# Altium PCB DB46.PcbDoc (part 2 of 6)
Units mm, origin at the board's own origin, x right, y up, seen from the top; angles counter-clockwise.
Board outline 82.2 x 113.2 mm, 8 copper layers (Top Layer, MidLayer1, MidLayer2, GND, MidLayer3, VCC, MidLayer4, Bottom Layer), stack 1.576 mm thick; 186 components, 477 nets, 1727 pads, 1538 vias.
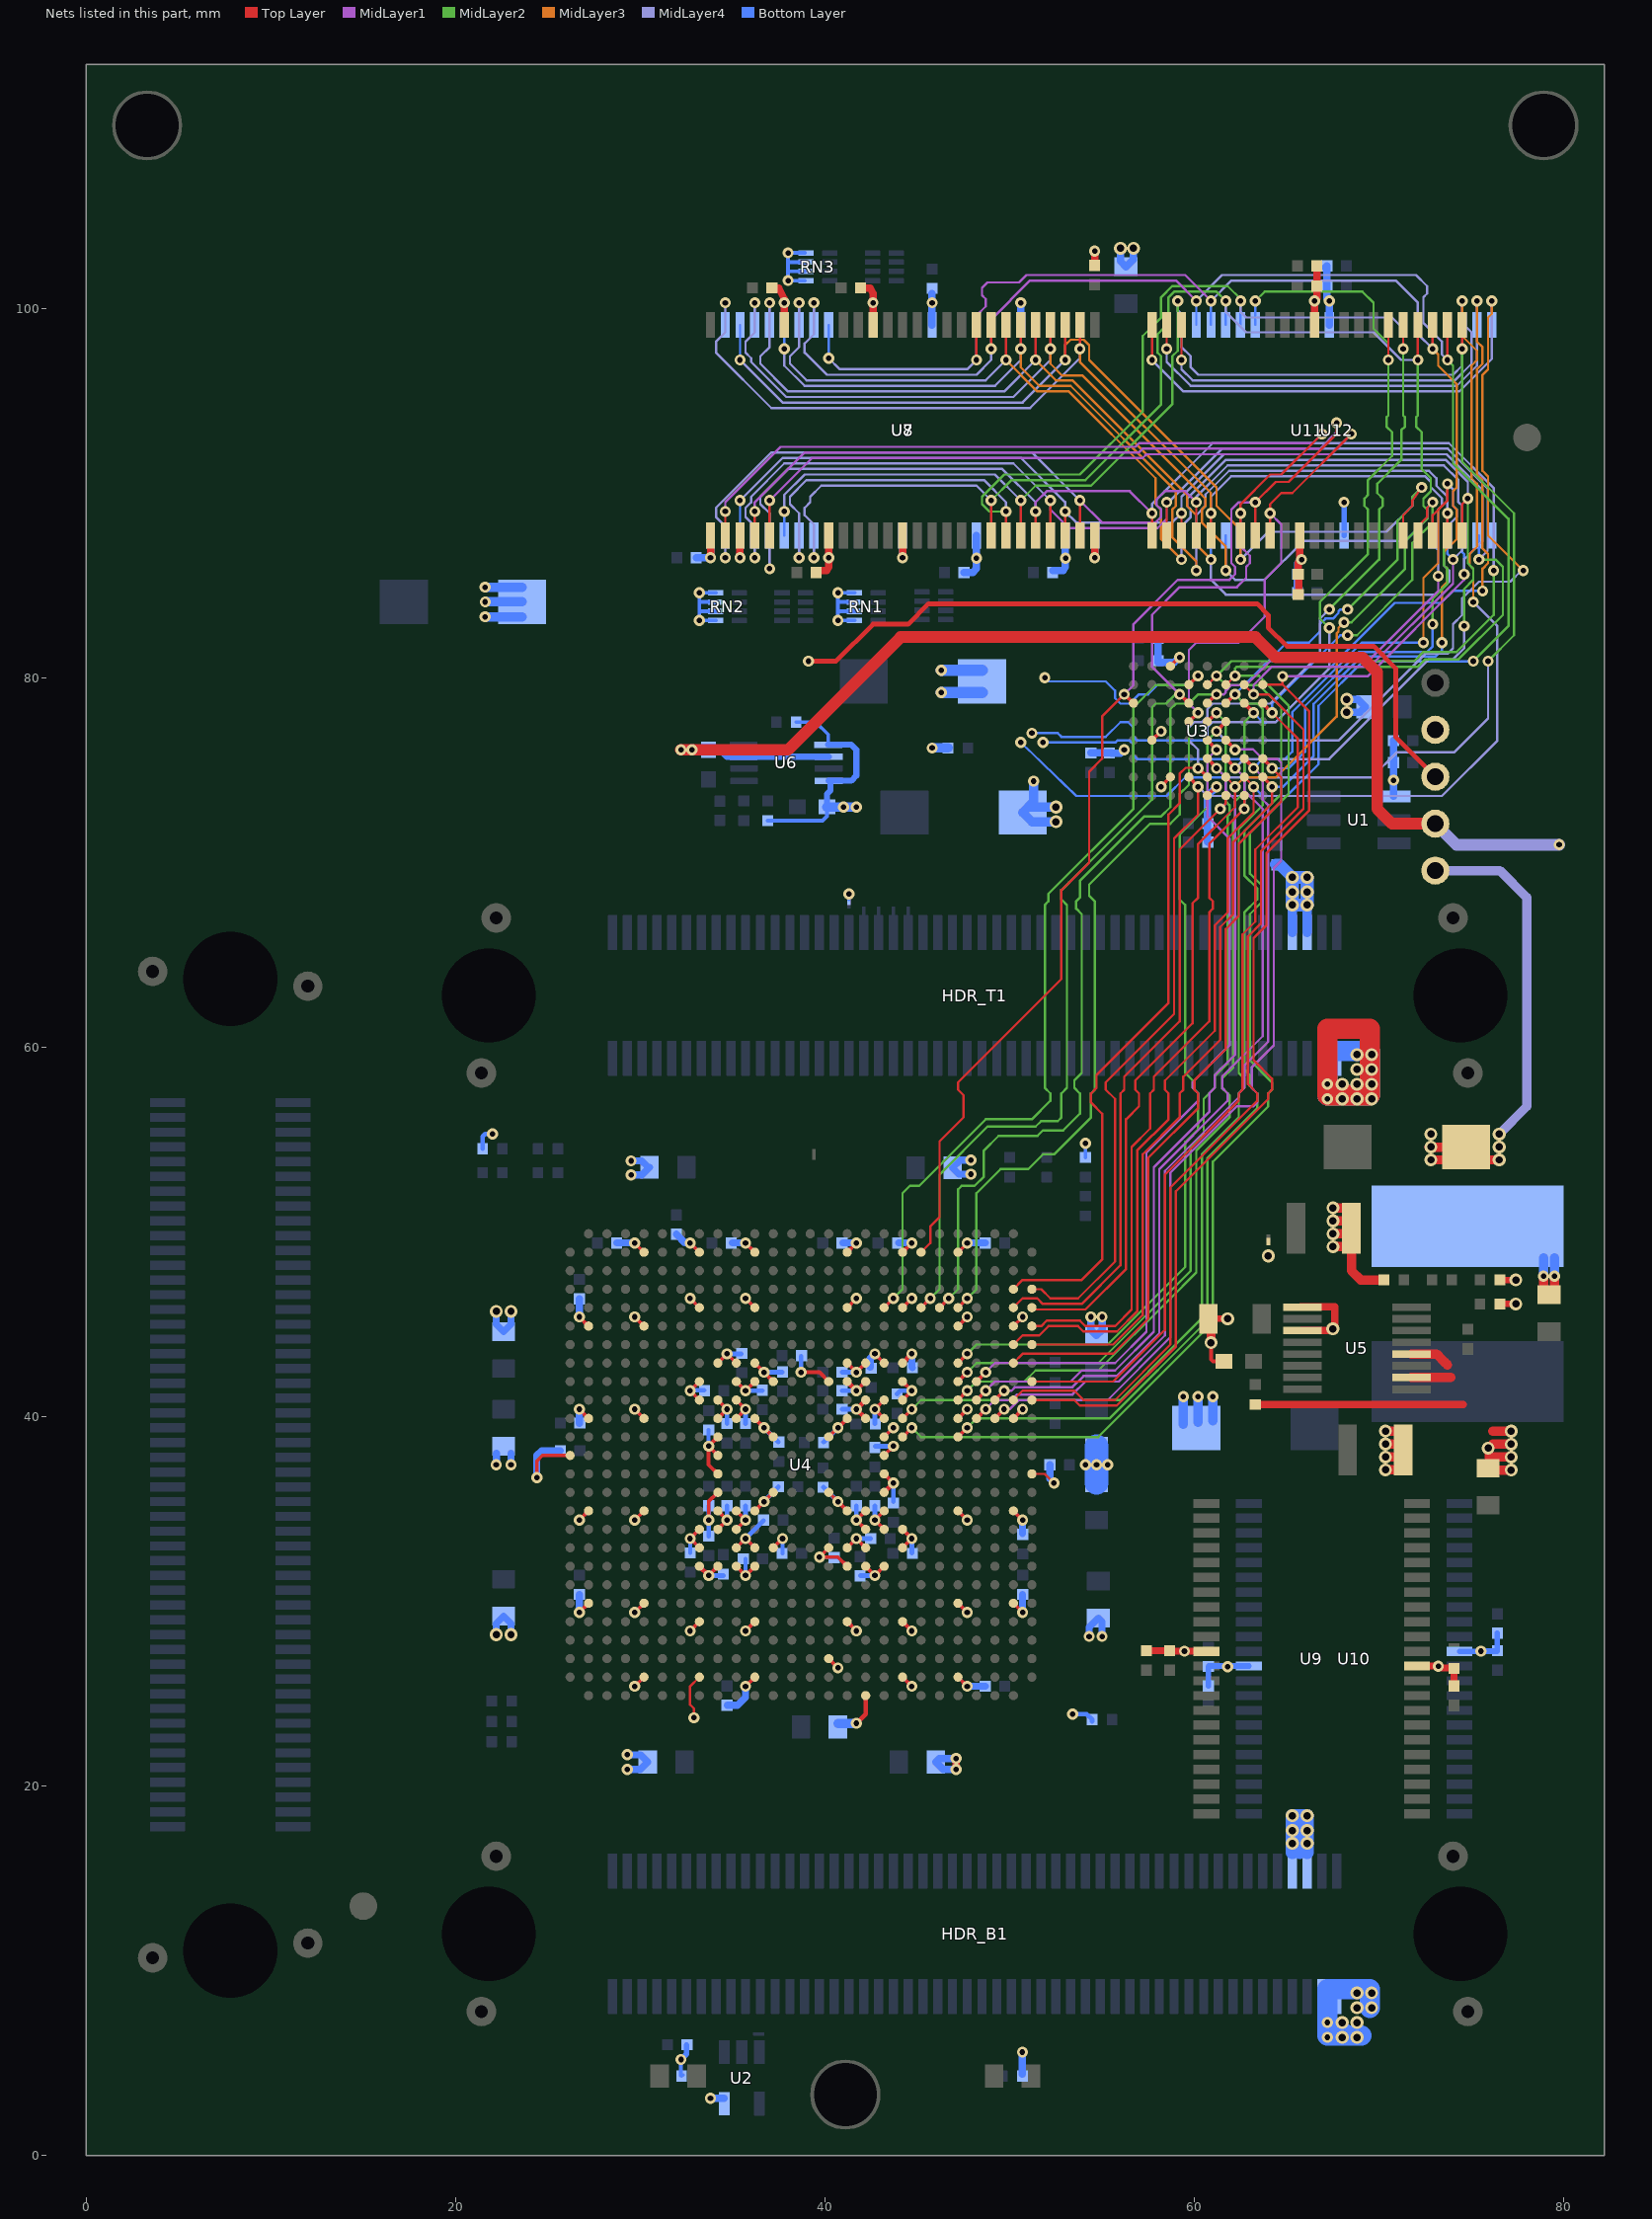
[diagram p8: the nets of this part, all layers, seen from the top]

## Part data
"Altium Logo Bot1" "Altium Logo Top1": library part D-000-0003, "Altium Logo for PCB"
C1 C7 C8 C9 C10 C11 C12 C13 C14 C25 C26 C27 C40 C41 C42 C43 C44 C71 C72 C73 C77 C91 C92 C93 C94 C99 C100 C103 C104 C107 C108 C109 C110: library part D-101-0080, "Capacitor, Ceramic, 0.1uF 10% 16V 0402 (1005) X7R"
C2 C15 C16 C17 C18 C19 C20 C21 C22 C28 C29 C30 C31 C45 C46 C47 C48 C49 C50 C51 C52 C53 C54 C55 C56 C57 C58 C59 C60 C61 C62 C63 C64 C65 C66 C67 C68 C74 C75 C76 C95 C96 C97 C98 C101 C102 C105 C106 C111 C112 C113 C114: library part D-101-0077, "Capacitor, Ceramic, 10nF 10% 16V 0402 (1005) X7R"
C3 C23 C69 C70 C82: library part D-101-0088, "Capacitor, Tantalum, 220uF 10% 10V MCCT-D (7343-31)"
C4 C5 C6 C24 C32 C33 C34 C35 C36 C37 C38 C39 C78 C79 C83 C85: library part D-101-0087, "Capacitor, Ceramic, 10uF 10% 10V 0805 (2012) X5R"
C80: library part D-101-0069, "Capacitor, Ceramic, 470pF 5% 50V 0402 (1005) COG"
C81 C88 C89: library part D-101-0095, "Capacitor, Ceramic, 2.2uF 10% 10V 0603 (1608) X5R"
C84 C86: library part D-101-0021, "Capacitor, Ceramic, 22uF -20%/+80% 10V 1210 (3225) Y5V"
C87: library part D-101-0027, "Capacitor, Ceramic, 1uF 10% 25V 1206 (3216) X7R"
C90: library part D-101-0105, "Capacitor, Ceramic, 0.033uF 10% 10V 0402 (1005) X7R"
FD1 FD2: library part D-000-0005, "Fiducial - Round 1.5mm Top-Bottom"
HDR_B1 HDR_L1 HDR_T1: library part D-300-0025, "Connector, Molex Docking Station 100 Pin Male 54075"
L1: library part D-102-0004, "Inductor, 2.2uH, 15A, 4R2, SMD"
LED1: library part D-153-0004, "LED, Green 0805 (2012) KP-2012SGD"
LED2: library part D-153-0003, "LED, Red 0805 (2013) HSMH-C170"
MH1 MH2 MH3: library part D-001-0001, "Mounting Hole, M3 Screw, Plated, Square Pad"
NT1 NT2 NT3 NT4 NT5 NT6 NT7 NT8: library part D-002-0002, "Net-Tie, Surface Mount, 2 x 0.4mm x 0.2mm SMT Pads - For 0.2mm Track"
PCB1: library part D-810-0034, "DB46 Blank PCB - Daughter Board"
R1 R2: library part D-100-0111, "Resistor, 270R 1% 0402 (1005)"
R3 R5 R8 R11: library part D-100-0088, "Resistor, 4K7 1% 0402 (1005)"
R4 R6 R7 R9 R10 R12 R13 R14 R15 R16 R17: library part D-100-0131, "Resistor, 100R 1% 0402 (1005)"
R22 R27 R28 R29: library part D-100-0132, "Resistor, 100K 1% 0402 (1005)"
R23: library part D-100-0128, "Resistor, 10R 1% 0402 (1005)"
R24 R26: library part D-100-0105, "Resistor, 2K7 1% 0402 (1005)"
R25: library part D-100-0109, "Resistor, 27K 1% 0402 (1005)"
RN1 RN2 RN3 RN4 RN5 RN6: library part D-104-0001, "Resistor Network, Isolated, 4 x 100R, 5%, SMD 0402 x 4"
TP1 TP2 TP3 TP4 TP5: library part D-006-0000, "Test Point, PCB Mount with Silkscreen Box"
U1: library part D-263-0002, "Dual Addressable Switch Plus 1KB Memory"
U2: library part D-205-0001, "SN74LVC1G04DBV, Single Inverter Gate, 1.65-V to 5.5-V"
U3: library part D-262-0001, "S29GL256N11FFIV10, 256 Megabit (16M x 16) 3.0V Page Mode Flash Memory"
U4: library part D-241-0021, "FPGA, Xilinx Virtex-4, XC4VSX35"
U5: library part D-204-0002, "MAX1831EEE, 3A, 1MHz, Low-Voltage, Step-Down Regulators with Synchronous Rectification and Internal Switches"
U6: library part D-204-0016, "MAX8860EUA18+, 1.8V Linear Regulator with adjustable Output, Low-noise, Low-dropout, 300mA, uMAX"
U7 U8: library part D-261-0000, "MT48LC16M16A2TG, 256 Mbit High-Speed CMOS SDRAM, 16Mb x 16Bit x 4 Banks, TSOP54"
U9 U10 U11 U12: library part D-260-0000, "K6R4016V1D-TC10T, 256K x 16-Bit SRAM, TSOP44"

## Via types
v1: diameter 0.6, hole 0.3, Top Layer to Bottom Layer, 904 vias
v2: diameter 0.6, hole 0.3, Top Layer to Bottom Layer, tented both sides, 506 vias
v3: diameter 0.7, hole 0.4, Top Layer to Bottom Layer, 127 vias
v4: diameter 0.6, hole 0.3, Top Layer to Bottom Layer, tented top, 1 vias

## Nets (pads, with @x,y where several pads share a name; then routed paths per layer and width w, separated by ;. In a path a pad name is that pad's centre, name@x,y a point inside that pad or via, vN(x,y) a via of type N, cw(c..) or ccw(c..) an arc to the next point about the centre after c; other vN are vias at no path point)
1V2: C3.1 C4.1 C5.1 C6.1 C7.1 C8.1 C9.1 C10.1 C11.1 C12.1 C13.1 C14.1 C15.1 C16.1 C17.1 C18.1 C19.1 C20.1 C21.1 C22.1 C82.1 C85.1 C86.1 L1.2 R24.1 TP5.1 U4.J10 U4.J11 U4.J16 U4.J17 U4.K9 U4.K10 U4.K17 U4.K18 U4.L9 U4.L10 U4.L11 U4.L16 U4.L17 U4.L18 U4.M12 U4.M15 U4.R12 U4.R15 U4.T9 U4.T10 U4.T11 U4.T16 U4.T17 U4.T18 U4.U9 U4.U10 U4.U17 U4.U18 U4.V10 U4.V11 U4.V16 U4.V17 | length 82.6
  Top Layer w0.2: U4.U9@34.2,33.9 v1(34.7,34.4) U4.T9@34.2,34.9 ; U4.L9@34.2,39.9 v1(34.7,40.4) U4.K9@34.2,40.9 ; U4.V10@35.2,32.9 v1(35.7,33.4) U4.V11@36.2,32.9 ; U4.U10@35.2,33.9 v1(35.7,34.4) U4.T10@35.2,34.9 ; U4.L10@35.2,39.9 v1(35.7,40.4) U4.K10@35.2,40.9 ; U4.J10@35.2,41.9 v1(35.7,41.4) U4.J11@36.2,41.9 ; U4.T11@36.2,34.9 v1(36.7,35.4) U4.R12@37.2,35.9 ; U4.L11@36.2,39.9 U4.M12@37.2,38.9 ; U4.R15@40.2,35.9 v1(40.7,35.4) U4.T16@41.2,34.9 ; U4.M15@40.2,38.9 U4.L16@41.2,39.9 ; U4.V16@41.2,32.9 v1(41.7,33.4) U4.V17@42.2,32.9 ; v1(41.7,41.4) U4.J17@42.2,41.9 ; U4.U17@42.2,33.9 v1(41.7,34.4) U4.T17@42.2,34.9 ; U4.U18@43.2,33.9 v1(42.7,34.4) U4.T18@43.2,34.9 ; U4.L18@43.2,39.9 v1(42.7,40.4) U4.K18@43.2,40.9
  Top Layer w0.254: U4.J16@41.2,41.9 v1(41.7,41.4) ; U4.L17@42.2,39.9 v1(41.7,40.4) U4.K17@42.2,40.9
  Top Layer w0.5: C86.1@68.4,50.2 C86.1@68.45,50.15 ; C86.1@68.5,49.5 68.5,50.2 68.5,47.9 69,47.4 R24.1@70.262,47.4 ; v3(72.8,53.9) C82.1@74,53.9 ; C82.1@74.709,53.9 v3(76.5,53.9) ; C82.1@74.709,54.6 C82.1@74.702,54.593 C82.1@75.395,53.9 ; C85.1@78.9,46.6 v1(78.9,47.6) ; C85.1@79.5,46.6 v1(79.5,47.6)
  Top Layer w0.508: v3(67.5,49.2) C86.1@68.5,49.2 ; v3(67.5,49.9) C86.1@68.5,49.9 ; v3(67.5,50.6) C86.1@68.5,50.6 ; v3(67.5,51.3) C86.1@68.5,51.3 ; v3@72.707,54.593 C82.1@74.702,54.593
  MidLayer4 w0.508: TP5.1@73.043,69.562 76.538,69.562 78,68.1 78,56.8 v3(76.5,55.3)
  Bottom Layer w0.2: v1(36.7,35.4) v1@36.7,35.425 ; v1@40.6,35.4 v1(40.7,35.4)
  Bottom Layer w0.254: v1(34.7,34.4) C19.1@34.7,35.175 ; C22.1@34.7,39.625 v1(34.7,40.4) ; v1(35.7,33.4) C11.1@36.675,34.375 ; v1(35.7,34.4) C20.1@35.7,35.175 ; C14.1@35.7,39.625 v1(35.7,40.4) ; v1(35.7,41.4) C18.1@36.6,41.4 ; v1@36.7,35.425 C9.1@37.475,36.2 ; v1(36.7,39.4) C13.1@37.475,38.625 ; C15.1@39.925,36.175 v1(40.7,35.4) ; C10.1@39.925,38.625 v1(40.7,39.4) ; C21.1@40.925,40.4 v1(41.7,40.4) ; C12.1@40.925,41.4 v1(41.7,41.4) ; v1(41.7,33.4) C7.1@42.475,33.4 ; v1(41.7,34.4) C8.1@41.7,35.175 ; v1(42.7,34.4) C16.1@42.7,35.175 ; C17.1@42.7,39.625 v1(42.7,40.4)
  Bottom Layer w0.4: v1(22.2,37.4) C4.1@22.2,38 ; v1(23,37.4) C4.1@23,38
  Bottom Layer w0.5: v1(78.9,47.6) L1.2@78.9,48.6 ; v1(79.5,47.6) L1.2@79.5,48.6
  Bottom Layer w0.508: C3.1@59.4,39.586 v1(59.4,41.086) ; C3.1@60.2,39.686 v1(60.2,41.086) ; C3.1@61,39.786 v1(61,41.086)
  Bottom Layer w1.27: C6.1@54.7,38.4 54.701,38.399 C5.1@54.701,36.4
  other v1: 54.1,37.4 54.701,37.4 55.3,37.4
  other v3: 72.8,54.6 76.5,54.6 72.8,55.3
2V5: C23.1 C24.1 C25.1 C26.1 C27.1 C28.1 C29.1 C30.1 C31.1 C88.1 R22.2 R28.1 TP3.1 U4.AF17 U4.H11 U4.H16 U4.H17 U4.J12 U4.M9 U4.N9 U4.N18 U4.P9 U4.P18 U4.R18 U4.V15 U4.W10 U4.W11 U4.W16 U6.1 U6.4 | length 81.1
  Top Layer w0.2: 33.7,37.4 U4.P9@34.2,36.9 ; v1(33.7,38.4) U4.N9@34.2,37.9 ; U4.H11@36.2,42.9 v1(36.7,42.4) U4.J12@37.2,41.9 ; U4.H16@41.2,42.9 v1(41.7,42.4) U4.H17@42.2,42.9 ; U4.N18@43.2,37.9 v1(43.7,38.4)
  Top Layer w0.203: 33.7,37.4 v1(33.7,38.4) U4.M9@34.2,38.9 ; U4.W10@35.2,31.9 v1(35.7,31.4) U4.W11@36.2,31.9 ; U4.V15@40.2,32.9 v1(39.7,32.4) 40.7,32.4 U4.W16@41.2,31.9 ; U4.P18@43.2,36.9 v1(43.7,36.4)
  Top Layer w0.254: v2(39.1,80.9) 40.6,80.9 42.6,82.9 44.5,82.9 45.6,84 63.4,84 64,83.4 64,82.7 65,81.7 69.7,81.7 70.9,80.5 70.9,77.331 70.9,76.785 TP3.1@73.043,74.642 ; v1(41.7,23.4) 42.2,23.9 U4.AF17@42.2,24.9 ; U4.R18@43.2,35.9 v1(43.7,36.4)
  Bottom Layer w0.2: v1(43.7,38.4) v1@43.7,38.6
  Bottom Layer w0.203: v1(33.7,38.4) C29.1@33.7,39.275 ; v1(35.7,31.4) C31.1@35.7,32.3 ; R22.2@36.9,72.262 39.862,72.262 40.1,72.5 C88.1@40.1,73 ; R28.1@38.438,77.6 39.5,77.6 40.175,76.925 U6.1@40.175,76.375 ; v1(39.7,32.4) C27.1@40.475,32.4
  Bottom Layer w0.254: v1(36.7,42.4) C28.1@37.675,42.4 ; C25.1@40.925,42.4 v1(41.7,42.4) ; C26.1@42.725,38.4 v1(43.7,38.4) ; C30.1@43.7,35.4 v1@43.7,36.175
  Bottom Layer w0.33: C88.1@40.1,73 40.1,73.7 40.3,73.9 U6.4@40.3,74.425 ; U6.1@40.175,76.375 41.425,76.375 41.7,76.1 41.7,74.7 41.425,74.425 U6.4@40.2,74.425
  Bottom Layer w0.508: C88.1@40.1,73 v2(41.7,73) ; C24.1@40.7,23.4 v1(41.7,23.4)
  Bottom Layer w0.635: v2(46.3,79.2) C23.1@48.5,79.2 ; v2(46.3,80.4) C23.1@48.5,80.4
  other v2: 41,73
3V3: C1.2 C2.1 C32.1 C33.1 C34.1 C35.1 C36.1 C37.1 C38.1 C39.1 C40.1 C41.1 C42.1 C43.1 C44.1 C45.1 C46.1 C47.1 C48.1 C49.1 C50.1 C51.1 C52.1 C53.1 C54.1 C55.1 C56.1 C57.1 C58.1 C59.1 C60.1 C61.1 C62.1 C63.1 C64.1 C65.1 C66.1 C67.1 C68.1 C69.1 C70.1 C71.2 C72.1 C73.1 C74.1 C75.1 C76.1 C77.1 C78.1 C79.1 C91.1 C92.1 C93.1 C94.1 C95.1 C96.1 C97.1 C98.1 C99.1 C100.1 C101.1 C102.1 C103.1 C104.1 C105.1 C106.1 C107.1 C108.1 C109.1 C110.1 C111.1 C112.1 C113.1 C114.1 HDR_B1.94 HDR_B1.96 HDR_T1.94 HDR_T1.96 NT1.2 R1.1 R2.1 R3.2 R5.2 R8.2 R11.2 RN1.1 RN1.2 RN1.3 RN1.4 RN2.1 RN2.2 RN2.3 RN2.4 RN3.1 RN3.2 RN3.3 RN3.4 TP2.1 U1.4 U2.5 U3.D8 U3.F1 U3.F7 U3.G5 U4.AA2 U4.AA5 U4.AA22 U4.AA25 U4.AB8 U4.AB11 U4.AB16 U4.AB19 U4.AD15 U4.AE5 U4.AE8 U4.AE11 U4.AE19 U4.AE22 U4.B5 U4.B8 U4.B11 U4.B16 U4.B19 U4.B22 U4.E8 U4.E11 U4.E16 U4.E19 U4.F2 U4.F5 U4.F22 U4.F25 U4.H9 U4.H10 U4.H18 U4.H19 U4.J8 U4.J15 U4.J19 U4.K8 U4.K19 U4.L2 U4.L5 U4.L22 U4.L25 U4.M18 U4.N1 U4.P26 U4.R9 U4.T2 U4.T5 U4.T22 U4.T25 U4.U8 U4.U19 U4.V8 U4.V12 U4.V19 U4.W8 U4.W9 U4.W17 U4.W18 U7.1 U7.3 U7.9 U7.14 U7.27 U7.43 U7.49 U8.1 U8.3 U8.9 U8.14 U8.27 U8.43 U8.49 U9.11 U9.33 U10.11 U10.33 U11.11 U11.33 U12.11 U12.33 | length 216.2
  Top Layer w0.127: v1(32.9,23.7) 32.9,24.2 32.7,24.4 32.7,25.4 U4.AE8@33.2,25.9 ; U7.9@40.2,87.2 U7.9@40.2,87.7 ; U4.P26@51.2,36.9 51.9,36.9 v1(52.4,36.4)
  Top Layer w0.178: v1(29.7,49.4) U4.B5@30.2,48.9 ; U4.B22@47.2,48.9 v1(47.7,49.4) ; U4.AA25@50.2,29.9 v1(50.7,29.4) ; U4.F25@50.2,44.9 v1(50.7,45.4)
  Top Layer w0.2: v1(24.4,36.7) 24.4,37.6 24.7,37.9 U4.N1@26.2,37.9 ; v1(26.7,29.4) U4.AA2@27.2,29.9 ; v1(26.7,34.4) U4.T2@27.2,34.9 ; v1(26.7,40.4) U4.L2@27.2,39.9 ; v1(26.7,45.4) U4.F2@27.2,44.9 ; v1(29.7,25.4) U4.AE5@30.2,25.9 ; v1(29.7,29.4) U4.AA5@30.2,29.9 ; v1(29.7,34.4) U4.T5@30.2,34.9 ; v1(29.7,40.4) U4.L5@30.2,39.9 ; v1(29.7,45.4) U4.F5@30.2,44.9 ; v1(32.7,28.4) U4.AB8@33.2,28.9 ; v1(32.7,46.4) U4.E8@33.2,45.9 ; v1(32.7,49.4) U4.B8@33.2,48.9 ; U4.V8@33.2,32.9 v1(32.7,33.4) U4.U8@33.2,33.9 ; U4.K8@33.2,40.9 v1(32.7,41.4) U4.J8@33.2,41.9 ; v1(33.7,34.4) 33.7,35.4 U4.R9@34.2,35.9 ; U4.H9@34.2,42.9 v1(34.7,43.4) U4.H10@35.2,42.9 ; v1(35.7,25.4) U4.AE11@36.2,25.9 ; v1(35.7,28.4) U4.AB11@36.2,28.9 ; v1(35.7,46.4) U4.E11@36.2,45.9 ; v1(35.7,49.4) U4.B11@36.2,48.9 ; U4.V12@37.2,32.9 v1(37.7,33.4) ; v1(38.7,42.4) 39.7,42.4 U4.J15@40.2,41.9 ; U4.AD15@40.2,26.9 v1(40.7,26.4) ; U4.AB16@41.2,28.9 v1(41.7,28.4) ; U4.E16@41.2,45.9 v1(41.7,46.4) ; U4.B16@41.2,48.9 v1(41.7,49.4) ; U4.W17@42.2,31.9 v1(42.7,31.4) U4.W18@43.2,31.9 ; v1(42.7,43.4) U4.H18@43.2,42.9 ; U4.M18@43.2,38.9 v1(43.7,39.4) ; U4.AE19@44.2,25.9 v1(44.7,25.4) ; U4.AB19@44.2,28.9 v1(44.7,28.4) ; U4.V19@44.2,32.9 v1(44.7,33.4) U4.U19@44.2,33.9 ; U4.K19@44.2,40.9 v1(44.7,41.4) U4.J19@44.2,41.9 ; U4.E19@44.2,45.9 v1(44.7,46.4) ; U4.B19@44.2,48.9 v1(44.7,49.4) ; U4.AE22@47.2,25.9 v1(47.7,25.4) ; U4.AA22@47.2,29.9 v1(47.7,29.4) ; U4.T22@47.2,34.9 v1(47.7,34.4) ; U4.L22@47.2,39.9 v1(47.7,40.4) ; U4.F22@47.2,44.9 v1(47.7,45.4) ; U4.T25@50.2,34.9 v1(50.7,34.4) ; U4.L25@50.2,39.9 v1(50.7,40.4) ; U3.G5@57.7,76.625 v1(58.2,77.1) ; v1@58.2,74.125 U3.F7@58.7,74.625 ; U3.F1@58.7,80.625 v1@59.2,81.125 ; U3.D8@60.7,73.625 v1@61.2,74.125
  Top Layer w0.203: v1(33.7,31.4) U4.W9@34.2,31.9
  Top Layer w0.254: U4.W8@33.2,31.9 v1(33.7,31.4) ; U4.H19@44.2,42.9 v1(44.7,43.4)
  Top Layer w0.381: v1(47.1,20.9) v1(47.1,21.5) ; C102.1@57.4,27.325 C100.1@58.652,27.325 58.672,27.305 59.512,27.305 59.517,27.3 U9.33@60.652,27.3 ; U9.11@72.052,26.5 73.3,26.5 73.4,26.4 74.027,26.4 C99.1@74.052,26.375 C101.1@74.052,25.425 ; v1@73.195,26.5 v1(73.203,26.492)
  Top Layer w0.4: v2@33.8,86.6 U7.1@33.8,87.7 ; v2(35.4,86.5) U7.3@35.4,87.7 ; C95.1@37.125,101.1 37.5,101.1 37.8,100.5 v2@37.8,100.2 ; U7.49@37.8,99.1 v2(37.8,100.3) ; C92.1@39.525,85.8 40.1,85.8 40.2,86 40.2,86.1 40.22,86.399 40.223,86.445 40.225,86.475 v2@40.219,86.504 ; U7.9@40.2,87.7 v2@40.2,86.6 ; C96.1@41.925,101.1 42.45,101.1 42.6,100.8 v2@42.6,100.2 ; U7.43@42.6,99.1 v2(42.6,100.3) ; v2(44.2,86.5) U7.14@44.2,87.7 ; v2(54.6,86.5) U7.27@54.6,87.7 ; C91.1@54.6,102.325 v2(54.6,103.1) ; C111.1@65.593,85.625 C111.1@65.618,85.6 65.618,86.218 v2(65.8,86.4) 65.7,86.5 U11.11@65.7,87.7 ; C107.1@65.643,84.575 65.643,85.6 C111.1@65.642,85.604 ; U11.33@66.5,99.1 v2(66.5,100.4) 66.625,100.525 C108.1@66.625,102.3 ; v2@40.2,86.6 v2@40.219,86.504 ; v2@40.2,86.6 v2@40.219,86.504
  MidLayer4 w0.127: v3@65.3,16.8 v3(65.3,16.9)
  Bottom Layer w0.2: v1@21.996,55.3 v1@21.996,55.321 ; v1(32.2,5.2) 32.2,4.338 R1.1@32.238,4.3 R1.1@32.3,4.362 ; C71.2@32.5,5.975 C71.2@32.525,6 ; C40.1@32.7,32.625 v1(32.7,33.4) ; 33.2,83.6 RN2.2@34.1,83.6 ; 33.2,84.1 RN2.3@34.1,84.1 ; RN2.1@34.1,83.1 v1(33.2,83.1) v1(33.2,84.6) RN2.4@34.1,84.6 ; U2.5@34.525,3.1 U2.5@34.55,3.125 ; C67.1@37.7,32.6 v1(37.7,33.4) ; 38,102 RN3.2@38.9,102 ; 38,102.5 RN3.3@38.9,102.5 ; RN3.1@38.9,101.5 v1(38,101.5) v1(38,103) RN3.4@38.9,103 ; 40.7,83.6 RN1.2@41.6,83.6 ; 40.7,84.1 RN1.3@41.6,84.1 ; NT1.2@41.3,68 v2(41.3,68.3) ; RN1.1@41.6,83.1 v1(40.7,83.1) v1(40.7,84.6) RN1.4@41.6,84.6 ; v1(47.1,21.5) v1@47.1,21.7 ; R5.2@54.1,54.038 v1(54.1,54.8) v1@54.1,54.9
  Bottom Layer w0.25: R3.2@21.462,54.5 21.462,55.162 21.6,55.3 v1@21.996,55.3 ; R11.2@54.462,23.5 R11.2@54.462,23.538
  Bottom Layer w0.254: v1@32.7,41.425 C53.1@33.45,41.425 ; v1(33.7,31.4) C56.1@34.5,31.4 ; C59.1@33.7,33.525 v1(33.7,34.4) C66.1@33.7,35.175 ; v1(34.7,43.4) C63.1@35.475,43.4 ; v1(38.7,42.4) C61.1@38.7,43.275 ; C58.1@41.925,31.4 v1(42.7,31.4) ; C52.1@43.9,41.225 44.075,41.4 v1(44.7,41.4) ; C65.1@44.7,32.625 v1(44.7,33.4) ; 52.176,36.624 v1(52.4,36.4) ; v1(53.4,23.9) 54.162,23.9 R11.2@54.462,23.6
  Bottom Layer w0.3: v1(32.2,5.2) 32.5,5.5 C71.2@32.5,5.975 ; C103.1@60.752,25.425 C105.1@60.752,26.475 60.777,26.5 U10.11@62.952,26.5 ; v1(61.798,26.467) v1@61.831,26.5 ; U12.11@68.1,87.7 v2(68.1,89.5) ; U10.33@74.352,27.3 75.509,27.3 v1(75.514,27.305) 76.38,27.305 C106.1@76.4,27.325 C104.1@76.4,28.275
  Bottom Layer w0.381: v3(22.2,28.2) 22.2,28.8 C35.1@22.6,29.2 23,28.8 v3(23,28.2) ; v3(22.2,45.7) 22.2,45 C33.1@22.6,44.6 23,45 v3(23,45.7) ; v1(24.4,36.7) 24.4,37.9 24.65,38.15 C55.1@25.674,38.15 ; v1(26.7,29.4) C57.1@26.699,30.375 ; v1(26.7,45.4) C44.1@26.699,46.375 ; C68.1@28.724,49.4 v1(29.7,49.4) ; v2(29.3,20.9) 30,20.9 C39.1@30.4,21.3 30,21.7 v2(29.3,21.7) ; v1(29.503,53.086) 30.086,53.086 C32.1@30.5,53.5 ; v1(29.503,53.848) 30.074,53.848 C32.1@30.404,53.518 ; C54.1@31.95,49.875 32.425,49.4 v1(32.7,49.4) ; C49.1@34.7,24.374 35.274,24.374 35.7,24.8 v1(35.7,25.4) ; C47.1@34.975,49.4 v1(35.7,49.4) ; C51.1@40.976,49.4 v1(41.7,49.4) ; C43.1@43.975,49.4 v1(44.7,49.4) ; v1(44.7,43.4) 44.7,42.675 C41.1@44.725,42.65 ; C38.1@46,21.3 46.4,20.9 v1(47.1,20.9) ; v1(47.7,49.4) C48.1@48.675,49.4 ; v1@47.701,25.399 C45.1@48.675,25.399 ; v1(47.9,53.127) 47.251,53.127 C34.1@46.903,53.474 47.317,53.889 v1(47.9,53.889) ; v1(50.7,29.4) C62.1@50.701,30.375 ; C64.1@50.701,33.675 v1(50.7,34.4) ; 52.176,36.624 C60.1@52.176,37.4 ; v1(54.3,28.1) 54.3,28.6 C37.1@54.8,29.1 55,28.9 v1(55,28.1)
  Bottom Layer w0.4: C42.1@26.7,39.65 v1(26.7,40.4) ; v1(32.7,41.4) v1@32.7,41.425 ; C93.1@33.025,86.5 v2(33.8,86.5) ; U8.27@33.775,87.325 U8.27@33.8,87.3 ; v1(33.8,3.1) U2.5@34.525,3.1 ; v2@33.8,86.475 U8.27@33.8,87.7 ; C50.1@42.45,42.675 42.45,43.15 v1(42.7,43.4) ; v2(44.2,86.5) U8.14@44.2,87.7 ; U8.43@45.8,99.1 C94.1@45.8,100.8 ; C38.1@46,21.3 46.2,21.5 v1(47.1,21.5) ; C98.1@47.525,85.7 48,85.7 48.2,85.9 v2(48.2,86.475) U8.9@48.2,87.7 ; U8.49@50.6,99.1 v2(50.6,100.3) ; R2.1@50.688,4.4 v1(50.688,5.6) ; C97.1@52.325,85.8 52.9,85.8 53,86 53,86.1 U8.3@53,87.7 ; v2@53,86.6 v2(53.025,86.475) ; v4(54.4,45.4) 54.4,44.7 C36.1@54.7,44.4 55,44.7 v1(55,45.4) ; C77.1@54.4,75.95 55.5,75.95 55.525,75.925 56,75.925 v1(56.2,76.1) ; v2(54.6,86.5) 54.6,86.6 U8.1@54.6,87.7 ; v3(56,103.25) 56,102.55 C79.1@56.3,102.25 56.7,102.65 v3(56.7,103.25) ; C73.1@58.025,81.925 58.025,80.825 58.9,80.825 v1@59.187,81.112 ; C72.1@60.725,71.1 60.7,71.125 60.7,73.6 v1@61.2,74.1 ; C109.1@65.575,84.6 C113.1@65.575,85.6 65.6,85.625 65.6,86.2 v2(65.8,86.4) ; C110.1@67.1,102.225 C110.1@67.175,102.3 67.175,100.525 v2(67.3,100.4) v2@67.3,100.5 ; U12.33@67.307,99.1 v2@67.307,100.2 ; v3(68.25,78.125) 68.95,78.125 C78.1@69.25,78.425 68.85,78.825 v3(68.25,78.825) ; U1.4@70.775,73.6 C1.2@70.775,76.6
  Bottom Layer w0.5: C70.1@50.995,73 v3(52.5,73) ; v1(51.3,74.4) 51.3,73.305 50.702,72.707 51.209,72.2 v3(52.5,72.2)
  Bottom Layer w0.508: v2(21.6,83.3) C69.1@23.6,83.3 ; v2(21.6,84.9) C69.1@23.6,84.9 ; v2(21.607,84.107) C69.1@23.602,84.107 ; v1(45.8,76.2) R8.2@46.662,76.2 ; HDR_T1.94@65.3,66.2 v3(65.3,68.4) ; HDR_T1.96@66.1,66.2 v3(66.1,68.4)
  Bottom Layer w0.635: C46.1@64.4,69.9 64.6,69.9 v3(65.3,69.2)
  Bottom Layer w0.7: 65.3,16.4 v3(65.3,18.4) v3(66.1,18.4) 66.1,16.4 ; 65.7,16.4 65.7,18.4 ; v3(65.3,67.7) v3(66.1,67.7) v3(66.1,69.2) v3(65.3,69.2) v3(65.3,67.7)
  other v1: 59.461,27.305 22,55.3 58.2,74.1 61.2,74.1 59.2,81.1
  other v2: 70.775,74.45 40.2,86.5 45.8,100.3
  other v3: 66.1,16.9 65.3,17.6 66.1,17.6
5V0: C83.1 C84.1 C89.1 HDR_B1.97 HDR_B1.99 HDR_T1.97 HDR_T1.99 R23.1 TP4.1 U5.2 U5.4 U6.2 U6.7 | length 121.6
  Top Layer w0.4: R23.1@63.262,40.7 R23.1@63.3,40.662 74.562,40.662 ; C83.1@75.9,37.2 v3(75.9,38.3)
  Top Layer w0.508: v3(70.35,38.519) C84.1@71.35,38.519 ; v3(70.35,39.219) C84.1@71.35,39.219 ; v3(70.35,37.119) C84.1@71.35,37.119 ; v3(70.35,37.819) C84.1@71.35,37.819 ; U5.2@71.744,42.132 73.868,42.132 ; U5.4@71.744,43.389 73.11,43.389 73.4,43.1 73.55,42.95 73.7,42.8 ; C83.1@76.15,37.112 v3(77.15,37.112) ; 76.15,37.812 v3(77.15,37.812) ; v3@76.15,38.512 v3(77.15,38.512) ; 76.15,39.212 v3(77.15,39.212)
  Top Layer w0.635: v2(32.2,76.1) 38,76.1 44.1,82.2 63.3,82.2 64.4,81.1 69.1,81.1 69.9,80.3 69.9,73.8 69.9,72.9 70.698,72.102 TP4.1@73.043,72.102
  Top Layer w1.1: v1@67.2,57.4 67.2,61 69.5,61 69.5,57.4 v1@67.2,57.4
  MidLayer4 w0.635: TP4.1@73.043,72.102 74.182,70.963 v1(79.746,70.963)
  Bottom Layer w0.33: C89.1@33.7,76.1 34.3,76.1 34.675,75.725 U6.2@40.2,75.725
  Bottom Layer w0.508: v2(32.2,76.1) C89.1@33.7,76.1
  Bottom Layer w1.1: 67.3,6.7 v3@68,6.7 ; v3@69,6.5 69.05,6.5 68.8,6.5 68,6.5 67.2,6.5 67.2,9 69.5,9 69.5,8.8 v3@69.5,8 ; v1@67.2,57.4 67.2,59.8 69.5,59.8 69.5,59.6 69.5,58.8 69.5,58 69.5,57.4 v1@67.2,57.4
  other v1: 67.2,6.4 67.2,7.2 67.2,57.2 67.2,58
  other v2: 32.8,76.1
  other v3: 68,6.4 68.8,6.4 68,7.2 68.8,7.2 68.8,8 69.6,8 68.8,8.8 69.6,8.8 68,57.2 68.8,57.2 69.6,57.2 68,58 68.8,58 69.6,58 68.8,58.8 69.6,58.8 68.8,59.6 69.6,59.6
AGND: C81.2 C87.1 NT8.1 R26.2 R27.2 U5.9 U5.11 | length 11
  Top Layer w0.2: v3(60.9,44) 60.9,43.1 61,43 C81.2@61.6,43
  Top Layer w0.35: C87.1@60.75,45.3 v3(61.8,45.3) ; R27.2@76.538,46.1 v3(77.4,46.1) ; R26.2@76.538,47.4 v3(77.4,47.4)
  Top Layer w0.4: U5.9@65.765,45.94 65.813,45.941 65.851,45.941 67.598,45.945 67.598,45.943 ; U5.11@65.813,44.659 U5.11@65.852,44.659 67.403,44.659 v3(67.493,44.749) ; 67.5,45.943 67.598,45.943 ; v3@67.598,44.749 67.598,44.66 67.598,45.943
  Top Layer w0.5: v3(60.9,44) 60.9,45.15 C87.1@60.75,45.3 C87.1@60.9,45.45
  other v3: 64,48.7
BUS_A1: U3.E2 U4.E18 | length 54.7
  Top Layer w0.2: U4.E18@43.2,45.9 v1(43.7,46.4) ; U3.E2@59.7,79.625 v1(60.2,80.1)
  MidLayer2 w0.127: v1(43.7,46.4) 44.2,46.9 44.2,51.5 44.2,51.8 44.2,52.1 44.6,52.5 45.1,52.5 46.4,53.8 48.7,56.1 51.2,56.1 52.2,57.1 52.2,57.5 51.9,57.8 51.9,67.7 52.1,67.9 52.1,68.3 56.7,72.9 56.7,78.4 57.9,79.6 59.7,79.6 v1(60.2,80.1)
  Bottom Layer w0.127: v1(51.9,80) 52.1,79.8 55.2,79.8 55.7,79.3 55.7,78.9 56,78.6 56.5,78.6 57,79.1 57.5,79.1 58,79.6 59.7,79.6 v1(60.2,80.1)
BUS_A2: U3.D2 U4.M22 U7.23 U8.23 U11.1 U12.1 | length 136.3
  Top Layer w0.127: U7.23@51.4,87.7 v2(51.4,89) ; U11.1@57.7,87.7 v1(57.7,88.9) ; U3.D2@60.7,79.625 60.725,79.625 v1(61.2,80.1)
  Top Layer w0.2: U4.M22@47.2,38.9 v1(47.7,39.4)
  MidLayer1 w0.127: v2(51.4,89) 51.4,89.5 52,90.1 56.5,90.1 v1(57.7,88.9)
  MidLayer2 w0.127: v1(47.7,39.4) 48.2,39.9 52.8,39.9 53.1,39.9 55.4,39.9 60.7,45.2 60.7,54 63.4,56.7 63.4,57.5 63,57.9 63,58.5 62.7,58.8 62.7,67.3 63.4,68 63.4,68.6 62.7,69.3 62.7,71.7 64.7,73.7 64.7,78.4 63.5,79.6 61.7,79.6 v1(61.2,80.1) 62,80.9 71.9,80.9 72.4,81.4 74.2,81.4 76.2,83.4 v1(76.2,85.8)
  MidLayer4 w0.127: v2(37,85.9) 37,88.9 36.5,89.4 36.5,89.8 38,91.3 49.6,91.3 51.4,89.5 v2(51.4,89) ; v1(57.7,88.9) 57.7,89.4 61,92.7 73.778,92.7 76.2,90.278 v1(76.2,85.8)
  Bottom Layer w0.127: v2(37,85.9) U8.23@37,87.7 ; v1(76.2,85.8) U12.1@76.2,87.7
BUS_A3: U3.C2 U4.M19 U7.24 U8.24 U11.2 U12.2 | length 140.3
  Top Layer w0.127: U7.24@52.2,87.7 v2(52.2,89.6) ; U11.2@58.5,87.7 v1(58.5,89.5) ; U3.C2@61.7,79.625 61.725,79.625 v1(62.2,80.1)
  Top Layer w0.178: U4.M19@44.2,38.9 v1(44.7,39.4)
  MidLayer1 w0.127: v2(52.2,89.6) 52.2,89.1 53.2,88.1 58,88.1 58.5,88.6 v1(58.5,89.5)
  MidLayer2 w0.127: v1(44.7,39.4) 45.2,38.9 52.8,38.9 53.1,38.9 54.8,38.9 61,45.1 61,53.8 64,56.8 64,57.5 64.2,57.7 64.2,58.1 63,59.3 63,67.2 63.7,67.9 63.7,68.7 63,69.4 63,71.6 65.1,73.7 65.1,78.5 63.5,80.1 v1(62.2,80.1) 62.2,80.5 62.3,80.6 72.1,80.6 72.5,81 74.3,81 76.7,83.4 76.7,86 76.3,86.4 v1(75.4,86.4)
  MidLayer4 w0.127: v2(36.2,86.5) 36.2,88.2 35.7,88.7 35.7,89.2 36,89.5 36,89.8 37.8,91.6 50.2,91.6 v2(52.2,89.6) ; v1(58.5,89.5) 58.6,89.5 61.5,92.4 73.718,92.4 75.87,90.249 75.87,86.87 v1(75.4,86.4)
  Bottom Layer w0.127: v2(36.2,86.5) U8.24@36.2,87.7 ; v1(75.4,86.4) U12.2@75.4,87.7
BUS_A4: U3.A2 U4.K26 U7.25 U8.25 U11.3 U12.3 | length 120.7
  Top Layer w0.127: U4.K26@51.2,40.9 52.8,40.9 53.1,40.9 53.5,40.9 53.8,40.6 55.8,40.6 59,43.8 59,52.2 64,57.2 64,57.5 64.2,57.7 64.2,58.3 63.2,59.3 63.2,65.9 63.9,66.6 63.9,70.5 66.2,72.8 66.2,78.2 64.775,79.625 ; U7.25@53,87.7 v2(53,89) ; U11.3@59.3,87.7 v1(59.3,88.9) ; U3.A2@63.7,79.625 64.775,79.625 ; v1(64.775,80.075) 64.775,79.625
  MidLayer1 w0.127: v1(64.775,80.075) 69.375,80.075 74.6,85.3 v1(74.6,85.6)
  MidLayer4 w0.127: v2(35.4,89.6) 37.7,91.9 50.612,91.9 53,89.513 v2(53,89) 53.6,88.4 58.8,88.4 v1(59.3,88.9) 59.3,89.8 61.6,92.1 73.659,92.1 75.59,90.169 75.59,87.401 74.6,86.411 v1(74.6,85.6)
  Bottom Layer w0.127: U8.25@35.4,87.7 v2(35.4,89.6) ; U12.3@74.5,87.125 U12.3@74.6,87.225 ; U12.3@74.5,87.7 74.5,86.8 74.6,86.7 v1(74.6,85.6)
BUS_A5: U3.B2 U4.K25 U7.26 U8.26 U11.4 U12.4 | length 126.1
  Top Layer w0.127: U4.K25@50.2,40.9 50.7,41.4 52.8,41.4 53.1,41.4 53.5,41.4 54,40.9 55.7,40.9 58.7,43.9 58.7,52.4 63.4,57.1 63.4,57.5 62.9,58 62.9,66 63.6,66.7 63.6,70.6 65.9,72.9 65.9,77.2 64,79.1 v1(63.2,79.1) 62.7,79.6 U3.B2@62.7,79.625 ; U7.26@53.8,87.7 v2(53.8,89.6) ; U11.4@60.1,87.7 v1(60.1,89.5)
  MidLayer1 w0.127: v2(53.8,89.6) 55,88.4 57.9,88.4 58.2,88.7 58.2,89.1 57.954,89.346 57.954,89.654 58.4,90.1 59.5,90.1 v1(60.1,89.5) ; v1(63.2,79.1) 63.2,79.6 64.2,80.6 69.5,80.6 74,85.1 v1(74,86.4)
  MidLayer4 w0.127: v2(34.6,86.5) 34.6,88.2 34.1,88.7 34.1,89.2 37.1,92.2 51.2,92.2 v2(53.8,89.6) ; v1(60.1,89.5) 60.1,89.8 61.8,91.5 73.5,91.5 74.287,90.712 74.287,89.512 74.5,89.3 74.5,86.9 v1(74,86.4)
  Bottom Layer w0.127: v2(34.6,86.5) U8.26@34.6,87.7 ; U12.4@73.8,87.6 U12.4@73.7,87.7 73.7,86.7 v1(74,86.4)
BUS_A6: U3.D3 U4.E21 U7.29 U8.29 U11.5 U12.5 | length 121.7
  Top Layer w0.127: v2(53.8,97.8) U7.29@53.8,99.1 ; U11.5@60.9,87.7 v1(60.9,88.9)
  Top Layer w0.2: U4.E21@46.2,45.9 v1(46.7,46.4) ; U3.D3@60.7,78.625 v1(61.2,79.1)
  MidLayer1 w0.127: v1(61.2,79.1) 61.6,79.1 61.7,79.2 61.7,79.3 62,79.6 62.8,79.6 64.1,80.9 69.4,80.9 73.2,84.7 v1(73.2,85.5)
  MidLayer2 w0.127: v1(46.7,46.4) 47.2,46.9 47.2,51.5 47.2,51.8 47.2,52.3 47.4,52.5 48.1,52.5 48.6,53 48.6,54.4 49.4,55.2 51.5,55.2 51.8,55.5 52.9,55.5 53.8,56.4 53.8,57.5 53.5,57.8 53.5,58.2 53.9,58.6 53.9,67.2 53.6,67.5 53.6,67.9 53.8,68.1 53.8,69 57.3,72.5 58.2,72.5 58.7,73 58.7,78.3 59,78.6 59.7,78.6 60.2,79.1 v1(61.2,79.1)
  MidLayer3 w0.127: v2(53.8,97.8) 53.8,97.1 60.9,90 v1(60.9,88.9)
  MidLayer4 w0.127: v2(34.6,100.3) 34.6,98.7 34.1,98.2 34.1,97.6 37.1,94.6 51.1,94.6 53.8,97.3 v2(53.8,97.8) ; v1(60.9,88.9) 60.9,89.812 61.987,90.9 72.5,90.9 72.8,90.6 72.8,90.319 73.4,89.719 73.4,89.3 73.2,89.1 v1(73.2,85.5)
  Bottom Layer w0.127: U8.29@34.6,99.1 v2(34.6,100.3) ; U12.5@72.9,87.7 72.9,87.2 73.2,86.9 v1(73.2,85.5)
BUS_A7: U3.C3 U4.L19 U7.30 U8.30 U11.18 U12.18 | length 129.2
  Top Layer w0.127: v2(53,97.2) U7.30@53,99.1 ; U11.18@71.3,87.7 71.3,88.8 71.8,89.3 71.8,89.6 v1(72.3,90.3)
  Top Layer w0.178: U4.L19@44.2,39.9 v1(44.7,40.4)
  Top Layer w0.2: U3.C3@61.7,78.625 v1(62.2,79.1)
  MidLayer2 w0.127: v1(44.7,40.4) 45.2,40.9 52.8,40.9 53.1,40.9 55.975,40.9 59,43.925 60.4,45.325 60.4,54.2 62.4,56.2 62.4,57.5 62.7,57.8 62.7,58.3 62.4,58.6 62.4,71.8 63.7,73.1 63.7,78.3 63.4,78.6 62.7,78.6 v1(62.2,79.1) ; v1(68.3,83.7) 71,86.4 71,88.5 71.8,89.3 71.8,89.8 v1(72.3,90.3)
  MidLayer3 w0.127: v2(53,97.2) 53,98 53.3,98.3 54,98.3 54.3,98 54.3,97.2 61.2,90.3 61.2,89.3 62.5,88 v2(62.5,86.4)
  MidLayer4 w0.127: v2(35.4,97.2) 37.7,94.9 50.7,94.9 v2(53,97.2) ; v2(62.5,86.4) 64,87.9 70.4,87.9 71.8,89.3 71.8,89.8 v1(72.3,90.3)
  Bottom Layer w0.127: v2(35.4,97.2) U8.30@35.4,99.1 ; v1(62.2,79.1) 65,81.9 66.2,81.9 66.8,82.5 66.8,82.9 67.1,83.2 67.5,83.2 67.8,83.5 67.8,83.6 67.9,83.7 v1(68.3,83.7) ; v2(62.5,86.4) U12.18@62.5,88.2
BUS_A8: U3.A3 U4.J26 U7.31 U8.31 U11.19 U12.19 | length 120.3
  Top Layer w0.127: U4.J26@51.2,41.9 52.8,41.9 53.1,41.9 55.6,41.9 58.4,44.7 58.4,53.1 62.4,57.1 62.4,57.5 62.6,57.7 62.6,66.1 63.3,66.8 63.3,70.7 65.6,73 65.6,76.7 v1(64.2,78.1) ; v2(52.2,97.8) U7.31@52.2,99.1 ; U11.19@72.1,87.7 72.1,88.2 72.6,88.7 72.6,89.2 v1(72.9,89.5)
  Top Layer w0.2: U3.A3@63.7,78.625 v1(64.2,78.1)
  MidLayer2 w0.127: v1(68.3,82.3) 68.8,82.3 71.8,85.3 71.8,87.3 72.9,88.4 v1(72.9,89.5)
  MidLayer3 w0.127: v2(52.2,97.8) 52.2,97 52.846,96.354 53.946,96.354 60.2,90.1 60.6,89.7 60.6,89.288 60.588,89.288 60.4,89.1 60.4,88.4 61.7,87.1 v1(61.7,85.8)
  MidLayer4 w0.127: v2(36.2,100.3) 36.2,98.7 35.7,98.2 35.7,97.6 36,97.3 36,97.1 37.9,95.2 50.2,95.2 52.2,97.2 v2(52.2,97.8) ; v1(61.7,85.8) 62.2,85.3 63.8,85.3 65.9,87.4 71.4,87.4 72.6,88.6 72.6,89.2 v1(72.9,89.5)
  Bottom Layer w0.127: U8.31@36.2,99.1 v2(36.2,100.3) ; v1(61.7,85.8) U12.19@61.7,87.7 ; v1(64.2,78.1) 64.2,78.6 67.9,82.3 v1(68.3,82.3)
BUS_A9: U3.B6 U4.L23 U7.32 U8.32 U11.20 U12.20 | length 132.2
  Top Layer w0.127: v2(51.4,97.2) U7.32@51.4,99.1 ; U11.20@72.9,87.7 72.9,88.8 73.7,89.6 v1(73.7,90.5)
  Top Layer w0.2: U4.L23@48.2,39.9 v1(48.7,40.4) ; U3.B6@62.7,75.625 v1@63.2,75.125
  MidLayer1 w0.127: v1(48.7,40.4) 49.2,40.9 50.1,40.9 50.4,41.2 52.8,41.2 53.1,41.2 53.4,41.2 54.1,41.9 55.9,41.9 58.4,44.4 58.4,53.3 62.409,57.309 62.409,57.49 62.4,57.5 62.7,57.8 62.7,59 64,60.3 64,69.4 ; v1@63.2,75.125 63.7,74.625 63.7,74.6 63.7,73.4 63.999,73.1 64,68.8
  MidLayer3 w0.127: v2(51.4,97.2) 52.5,96.1 53.4,96.1 53.9,95.6 59.6,89.9 59.6,89.3 60.1,88.8 60.1,87.2 v2(60.9,86.4) ; v1(72.4,81.9) 72.4,85.4 73.2,86.2 73.2,89.1 73.7,89.6 ; 73.7,89.6 v1(73.7,90.5)
  MidLayer4 w0.127: v2(37,100.3) 37,97.9 36.5,97.4 36.5,97 38,95.5 49.7,95.5 v2(51.4,97.2) ; v2(60.9,86.4) 60.9,85.3 61.7,84.5 73.1,84.5 73.8,85.2 73.8,85.8 73.5,86.1 73.5,88 74.2,88.7 74.2,89.1 74,89.3 74,90.2 v1(73.7,90.5)
  Bottom Layer w0.127: U8.32@37,99.1 v2(37,100.3) ; v2(60.9,86.4) U12.20@60.9,87.7 ; v1(63.2,75.1) 63.7,75.6 64.9,75.6 65.3,76 65.3,78.141 69.059,81.9 v1(72.4,81.9)
BUS_A10: U3.A6 U4.H25 U7.33 U8.33 U11.21 U12.21 | length 120.9
  Top Layer w0.127: U4.H25@50.2,42.9 50.7,43.4 52.8,43.4 53.1,43.4 55.6,43.4 57.5,45.3 57.5,54 60.2,56.7 60.2,57.5 60,57.7 60,58.2 61.7,59.9 61.7,66.4 62.4,67.1 62.4,69.904 ; v2(50.6,97.8) U7.33@50.6,99.1 ; 62.4,69.6 62.4,71 64.7,73.3 64.7,74.6 v1(64.2,75.1) v1@64.2,75.125 ; U11.21@73.7,87.7 v1(73.7,88.9)
  Top Layer w0.2: U3.A6@63.7,75.625 v1@64.2,75.125
  MidLayer2 w0.127: v1(72.9,82.9) 72.9,84.3 73.7,85.1 73.7,85.9 73.5,86.1 73.5,88.1 73.7,88.3 v1(73.7,88.9)
  MidLayer3 w0.127: v2(50.6,97.8) 50.6,96.8 51.6,95.8 53.3,95.8 59,90.1 59,89.3 58.8,89.1 58.8,87.6 60.1,86.3 v1(60.1,85.8)
  MidLayer4 w0.127: v2(37.8,97.8) 37.8,96.9 38.9,95.8 49.2,95.8 50.6,97.2 v2(50.6,97.8) ; v1(60.1,85.8) 60.1,88.8 60.588,89.288 60.6,89.288 60.6,89.919 61.881,91.2 72.7,91.2 73.1,90.8 73.1,90.4 73.7,89.8 v1(73.7,88.9)
  Bottom Layer w0.127: v2(37.8,97.8) U8.33@37.8,99.1 ; v1(60.1,85.8) U12.21@60.1,87.7 ; v1(64.2,75.1) 65.1,75.1 66,76 66,78.481 68.918,81.4 72.6,81.4 72.9,81.7 v1(72.9,82.9)
BUS_A11: U3.C6 U4.K24 U7.34 U8.34 U11.22 U12.22 | length 127.8
  Top Layer w0.127: v2(49.8,97.2) U7.34@49.8,99.1 ; U11.22@74.5,87.7 74.5,89.4 v1(74.8,89.7)
  Top Layer w0.2: U4.K24@49.2,40.9 v1(49.7,41.4) ; U3.C6@61.7,75.625 v1@62.2,75.125
  MidLayer1 w0.127: v1(49.7,41.4) 50.1,41.4 50.3,41.6 52.8,41.6 53.1,41.6 53.4,41.6 54,42.2 55.8,42.2 58.1,44.5 58.1,53.4 61.8,57.1 61.8,57.5 61.5,57.8 61.5,58.4 63.7,60.6 63.7,72.9 62.7,73.9 62.7,74.625 v1@62.2,75.125
  MidLayer2 w0.127: v1(74.6,82.8) 74.6,84.8 75.1,85.3 75.1,85.9 74.8,86.2 v1(74.8,89.7)
  MidLayer3 w0.127: v2(49.8,97.2) 51.5,95.5 53.2,95.5 57.9,90.8 57.9,89.4 58.2,89.1 58.2,87.5 v2(59.3,86.4)
  MidLayer4 w0.127: v2(38.6,100.3) 38.6,97.9 38.1,97.4 38.1,97 39,96.1 48.7,96.1 v2(49.8,97.2) ; v2(59.3,86.4) 59.3,88.2 59.8,88.7 59.8,89.1 59.6,89.3 59.6,89.7 61.7,91.8 73.6,91.8 74.8,90.6 v1(74.8,89.7) ; v1(62.2,75.1) 62.7,75.6 67.3,75.6 72.7,81 74,81 74.6,81.6 v1(74.6,82.8)
  Bottom Layer w0.127: U8.34@38.6,99.1 v2(38.6,100.3) ; v2(59.3,86.4) U12.22@59.3,87.7
BUS_A12: U3.D6 U4.K23 U7.22 U8.22 U11.23 U12.23 | length 139.2
  Top Layer w0.127: U7.22@50.6,87.7 v2(50.6,89.6) ; v2(74.5,97.8) U11.23@74.5,99.1
  Top Layer w0.2: U4.K23@48.2,40.9 v1(48.7,41.4) ; U3.D6@60.7,75.625 v1@61.2,75.125
  MidLayer1 w0.127: v1(48.7,41.4) 49.2,41.9 52.8,41.9 53.1,41.9 53.3,41.9 53.9,42.5 55.7,42.5 57.8,44.6 57.8,53.5 60.8,56.5 60.8,57.5 61.1,57.8 61.1,58.5 61.4,58.8 61.8,59.201 62.2,59.6 62.2,73.4 61.7,73.9 61.7,74.6 v1(61.2,75.1) 61.2,75.125 v1@61.213,75.113
  MidLayer2 w0.127: v2(50.6,89.6) 51.4,90.4 54.4,90.4 58.8,94.8 58.8,97.4 59.1,97.7 v2(59.1,100.4) ; v2(74.5,97.8) 74.5,91.7 77.3,88.9 77.3,82.3 v1(75.9,80.9)
  MidLayer4 w0.127: v2(37.8,89) 37.8,89.9 38.9,91 49.2,91 v2(50.6,89.6) ; v2(59.1,100.4) 59.1,99.9 59.3,99.7 59.3,97.9 59.8,97.4 59.8,96.8 60.2,96.4 74,96.4 74.5,96.9 v2(74.5,97.8) ; v1(61.2,75.1) 61.7,74.6 69.6,74.6 70.974,75.974 74.074,75.974 75.9,77.8 v1(75.9,80.9)
  Bottom Layer w0.127: U8.22@37.8,87.7 v2(37.8,89) ; v2(59.1,100.4) 59.1,99.8 59.3,99.6 U12.23@59.3,99.1
BUS_A13: U3.B7 U4.G25 U7.35 U8.35 U11.24 U12.24 | length 127.6
  Top Layer w0.127: v2(49,97.8) U7.35@49,99.1 ; U4.G25@50.2,43.9 50.7,44.4 51.6,44.4 52.1,44.9 52.8,44.9 53.1,44.9 53.7,44.9 53.987,44.612 55.812,44.612 56.9,45.7 56.9,54.4 58.6,56.1 58.6,57.5 58.4,57.7 58.4,58.187 61.1,60.887 61.1,66.6 61.8,67.3 61.8,71.3 63.2,72.7 63.2,74.125 U3.B7@62.7,74.625 ; v2(73.7,97.2) U11.24@73.7,99.1
  MidLayer1 w0.127: v2(49,97.8) 49,99.4 51.1,101.5 59,101.5 v2(60.1,100.4)
  MidLayer2 w0.127: v2(73.7,97.2) 74,96.9 74,91.6 77,88.6 77,82.8 v1(75.1,80.9)
  MidLayer4 w0.127: v2(39.4,100.3) 39.4,98.6 38.9,98.1 38.9,97.6 40.1,96.4 48.2,96.4 49,97.2 v2(49,97.8) ; v2(60.1,100.4) 61.5,101.8 72,101.8 72.6,101.2 72.6,100.8 72.4,100.6 72.4,99.2 73.4,98.2 73.4,97.5 v2(73.7,97.2)
  Bottom Layer w0.127: U8.35@39.4,98.6 39.4,99.1 v2(39.4,100.3) ; U12.24@60.1,99.1 v2(60.1,100.4) ; v1(63.2,74.1) 63.7,73.6 65,73.6 66.713,75.313 66.713,78.476 69.129,80.892 75.092,80.892 v1(75.1,80.9)
BUS_A14: U3.A7 U4.G26 U7.36 U8.36 U11.25 U12.25 | length 117.5
  Top Layer w0.127: v2(48.2,97.2) U7.36@48.2,99.1 ; U4.G26@51.2,43.9 52.8,43.9 53.1,43.9 55.6,43.9 57.2,45.5 57.2,54.2 59.2,56.2 59.2,57.5 59.4,57.7 59.4,58.4 61.4,60.4 61.4,66.5 62.1,67.2 62.1,71.1 64.2,73.2 v1@64.2,74.125 ; v2(72.9,97.8) U11.25@72.9,99.1
  Top Layer w0.2: U3.A7@63.7,74.625 v1@64.2,74.125
  MidLayer1 w0.127: v2(48.2,97.2) 48.2,99.6 48.7,100.1 48.7,100.5 48.5,100.7 48.5,101.1 48.8,101.4 50.5,101.4 50.9,101.8 59.5,101.8 v2(60.9,100.4)
  MidLayer3 w0.127: v2(72.9,97.8) 73.2,97.5 73.2,96.9 74.2,95.9 74.2,90.3 74,90.1 74,89.3 74.2,89.1 74.2,87.5 73.5,86.8 73.5,86.1 73.7,85.9 73.7,85.2 73.4,84.9 v1(73.4,81.9)
  MidLayer4 w0.127: v2(40.2,97.3) 40.8,96.7 47.7,96.7 v2(48.2,97.2) ; v2(60.9,100.4) 62,101.5 70.9,101.5 72.1,100.3 72.1,98.6 v2(72.9,97.8)
  Bottom Layer w0.127: v2(40.2,97.3) U8.36@40.2,99.1 ; U12.25@60.9,99.1 v2(60.9,100.4) ; v1(64.2,74.1) 64.8,74.1 66.459,75.759 66.459,78.581 69.024,81.146 73.046,81.146 73.4,81.5 v1(73.4,81.9)
BUS_A15: U3.C7 U4.E26 U7.20 U8.20 U11.26 U12.26 | length 118.1
  Top Layer w0.127: U7.20@49,87.7 v2(49,89.6) ; U4.E26@51.2,45.9 51.3,45.8 52.8,45.8 53.1,45.8 54.1,45.8 56.3,48 56.3,56.1 57,56.8 57,57.5 56.8,57.7 56.8,58.2 59.9,61.3 59.9,67.8 60.2,68.1 60.2,71 62.2,73 v1(62.2,74.1) 62.2,74.125 U3.C7@61.7,74.625 ; v2(72.1,97.2) U11.26@72.1,99.1
  MidLayer2 w0.127: v2(49,89.6) 50.1,90.7 54.1,90.7 58.2,94.8 58.2,97.4 58,97.6 58,98.6 58.25,98.85 58.6,99.2 58.6,100.6 58.9,100.9 61.2,100.9 v2(61.7,100.4) ; v1(68.1,83) 68.5,83 71.4,85.9 71.4,87.4 72.6,88.6 72.6,89.1 72.4,89.3 72.4,89.7 72.8,90.1 72.8,90.8 72.3,91.3 72.3,93.3 72,93.6 72,94.1 72.1,94.2 v2(72.1,97.2)
  MidLayer3 w0.127: v1(62.2,74.1) 62.7,74.6 64.4,74.6 67.7,77.9 67.7,82.4 67.8,82.5 67.8,82.7 v1(68.1,83)
  MidLayer4 w0.127: v2(39.4,86.5) 39.4,88.3 38.9,88.8 38.9,89.2 39.2,89.5 39.2,89.8 39.8,90.4 48.2,90.4 v2(49,89.6) ; v2(61.7,100.4) 61.7,99.8 62.8,98.7 69.7,98.7 71.2,97.2 v2(72.1,97.2)
  Bottom Layer w0.127: v2(39.4,86.5) U8.20@39.4,87.7 ; U12.26@61.7,99.1 v2(61.7,100.4)
BUS_A16: U3.D7 U4.D25 U7.21 U8.21 U11.27 U12.27 | length 122.5
  Top Layer w0.127: U7.21@49.8,87.7 v2(49.8,89) ; U4.D25@50.2,46.9 50.7,47.4 52.8,47.4 53.1,47.4 53.9,47.4 55,48.5 55,56.4 54.4,57 54.4,57.5 54.7,57.8 54.7,58.5 58.6,62.4 58.6,72.6 59.2,73.2 59.2,74.8 59.525,75.125 v1@60.2,75.125 ; v2(71.3,97.8) U11.27@71.3,99.1
  Top Layer w0.2: v1@60.2,75.125 60.213,75.113 U3.D7@60.7,74.625
  MidLayer2 w0.127: v2(49.8,89) 48.9,89 48.5,89.4 48.5,89.8 48.9,90.2 49.7,91 53.8,91 57.2,94.4 57.2,98.5 58.2,99.5 58.2,100.6 58.8,101.2 61.8,101.2 62.5,100.5 v2(62.5,100.4) ; v1(67.3,83.7) 70,86.4 70,89.1 70.2,89.3 70.2,89.7 69.9,90 69.9,90.5 71.2,91.8 71.2,93.4 71.4,93.6 71.4,94.1 71.3,94.2 v2(71.3,97.8)
  MidLayer4 w0.127: v2(38.6,86.5) 38.6,88.9 38.1,89.4 38.1,89.8 39,90.7 48.6,90.7 49.8,89.5 v2(49.8,89) ; v1(60.2,75.1) 60.2,76.1 59.7,76.6 59.7,77.3 60,77.6 60.4,77.6 60.7,77.9 60.7,78.3 61,78.6 64.1,78.6 66.8,81.3 66.8,83.2 v1(67.3,83.7) ; v2(62.5,100.4) 62.5,99.8 62.8,99.5 70.7,99.5 71.3,98.9 v2(71.3,97.8)
  Bottom Layer w0.127: v2(38.6,86.5) U8.21@38.6,87.7 ; U12.27@62.5,99.1 v2(62.5,100.4)
BUS_A17: U3.E7 U4.D26 U11.42 U12.42 | length 100.7
  Top Layer w0.127: U4.D26@51.2,46.9 51.7,46.9 52.2,46.4 52.8,46.4 53.1,46.4 53.7,46.4 55.7,48.4 55.7,57.2 55.2,57.7 55.2,58.1 58.9,61.8 58.9,71.3 60.2,72.6 v1(60.2,74.1) ; v2(59.3,97.2) U11.42@59.3,99.1
  Top Layer w0.2: U3.E7@59.7,74.625 v1(60.2,74.1)
  MidLayer3 w0.127: v2(74.5,100.4) 74.5,98.5 75.3,97.7 75.3,97.2 75,96.9 75,90.8 75.3,90.5 75.3,87.1 74.9,86.7 74.9,86.1 75.1,85.9 v1(75.1,84.1)
  MidLayer4 w0.127: v2(59.3,97.2) 59.3,96.7 59.9,96.1 74.1,96.1 75,97 75,98.7 74.5,99.2 v2(74.5,100.4) ; v1(60.2,74.1) 60.7,73.6 73.4,73.6 76.4,76.6 76.4,82.8 v1(75.1,84.1)
  Bottom Layer w0.127: U12.42@74.5,99.1 v2(74.5,100.4)
BUS_A18: U3.B3 U4.K22 U11.43 U12.43 | length 104.9
  Top Layer w0.127: v2(58.5,97.8) U11.43@58.5,99.1 ; v1(63.2,78.1) v1@63.2,78.125
  Top Layer w0.2: U4.K22@47.2,40.9 v1(47.7,41.4) ; U3.B3@62.7,78.625 v1@63.2,78.125
  MidLayer2 w0.127: v1(47.7,41.4) 48.2,41.9 50.8,41.9 51.4,42.5 52.8,42.5 53.1,42.5 54.8,42.5 58.6,46.3 60.1,47.8 60.1,54.4 61.9,56.2 61.9,57.4 61.5,57.8 61.5,58.3 62.1,58.9 62.1,67.9 62.1,72.2 62.2,72.3 62.2,73.3 62.7,73.8 62.7,75.6 62.7,77.6 v1(63.2,78.1)
  MidLayer3 w0.127: v2(75.3,100.4) 75.3,98.2 75.6,97.9 75.6,97 75.3,96.7 75.3,91 75.6,90.7 75.6,87 75.9,86.7 75.9,86.2 75.6,85.9 v1(75.6,84.7)
  MidLayer4 w0.127: v2(58.5,97.8) 58.5,97.1 59.8,95.8 74.2,95.8 75.3,96.9 v2(75.3,100.4)
  Bottom Layer w0.127: v1(63.2,78.1) 63.7,77.6 64.4,77.6 70.85,84.05 73.35,84.05 74,84.7 v1(75.6,84.7) ; U12.43@75.3,99.1 v2(75.3,100.4)
BUS_A19: U3.C4 U4.H22 U11.44 U12.44 | length 109.5
  Top Layer w0.127: v2(57.7,97.2) U11.44@57.7,99.1
  Top Layer w0.2: U4.H22@47.2,42.9 v1(47.7,43.4) ; v1(61.2,77.1) U3.C4@61.7,77.625
  MidLayer2 w0.127: v1(47.7,43.4) 48.2,43.9 52.8,43.9 53.1,43.9 55.3,43.9 59.5,48.1 59.5,54.875 60.2,55.575 60.2,57.5 59.9,57.8 59.9,58.2 59.5,58.6 59.5,67.7 59.2,68 59.2,71.5 60.7,73 60.7,76.6 v1(61.2,77.1)
  MidLayer3 w0.127: v2(76.1,100.4) 76.1,99.7 75.9,99.5 75.9,96.7 75.6,96.4 75.6,91.2 75.9,90.9 75.9,87.7 76.1,87.5 v1(77.8,85.8)
  MidLayer4 w0.127: v2(57.7,97.2) 59.4,95.5 74.337,95.5 76.1,97.262 v2(76.1,100.4) ; v1(61.2,77.1) 61.7,76.6 67.8,76.6 72.5,81.3 73.7,81.3 74,81.6 74,82.9 74.5,83.4 74.5,84.3 75.4,85.2 77.1,85.2 77.7,85.8 v1(77.8,85.8)
  Bottom Layer w0.127: U12.44@76.1,99.1 v2(76.1,100.4)
BUS_A20: U3.D5 U4.J23 U11.28 U12.28 | length 87
  Top Layer w0.127: v2(70.5,97.2) U11.28@70.5,99.1
  Top Layer w0.2: U4.J23@48.2,41.9 v1(48.7,42.4) ; U3.D5@60.7,76.625 v1(61.2,76.1)
  MidLayer1 w0.127: v1(48.7,42.4) 49.2,42.9 52.8,42.9 53.1,42.9 55.7,42.9 57.4,44.6 57.4,54.3 60.2,57.1 60.2,57.5 59.9,57.8 59.9,58.1 61.9,60.1 61.9,71.3 60.7,72.5 60.7,75.6 v1(61.2,76.1)
  MidLayer2 w0.127: v2(63.3,100.4) 63.8,100.9 69.1,100.9 69.7,100.3 69.7,98.9 70.5,98.1 70.5,94.2 70.4,94.1 70.4,93.6 70.7,93.3 70.7,92 69.4,90.7 69.4,89.9 69.2,89.7 69.2,89.3 69.4,89.1 69.4,86.7 66.8,84.1 66.8,83.2 v1(67.3,82.7)
  MidLayer4 w0.127: v1(61.2,76.1) 60.7,76.6 60.7,77.3 61,77.6 64.4,77.6 67.3,80.5 v1(67.3,82.7)
  Bottom Layer w0.127: U12.28@63.3,99.1 v2(63.3,100.4)
BUS_A21: U3.D4 U4.J22 | length 47.1
  Top Layer w0.2: U4.J22@47.2,41.9 v1(47.7,42.4) ; U3.D4@60.7,77.625 v1(61.2,78.1)
  MidLayer2 w0.127: v1(47.7,42.4) 48.2,42.9 52.8,42.9 53.1,42.9 54.8,42.9 59.8,47.9 59.8,54.625 60.5,55.325 60.5,57.2 61.1,57.8 61.1,58.4 61.8,59.1 61.8,69.825 61.8,72.5 61.9,72.6 61.9,73.1 61.7,73.3 61.7,73.9 61.7,77.6 v1(61.2,78.1)
BUS_A22: U3.C5 U4.L24 | length 61.5
  Top Layer w0.2: U4.L24@49.2,39.9 v1(49.7,40.4) ; U3.C5@61.7,76.625 v1@62.2,76.125
  MidLayer1 w0.127: v1(49.7,40.4) 50,40.4 50.5,40.9 52.8,40.9 53.1,40.9 55.3,40.9 58.7,44.3 58.7,53.2 62.3,56.8 63.2,56.8 63.4,57 63.4,57.5 63.1,57.8 63.1,58.9 64.3,60.1 64.3,69.7 64.7,70.1 64.7,75.4 64.5,75.6 63.7,75.6 63.175,76.125 v1@62.2,76.125
  Bottom Layer w0.127: v1(51.2,77) 52.6,77 52.8,76.8 55.2,76.8 56,77.6 56.4,77.6 56.7,77.3 56.7,76.8 56.9,76.6 61.7,76.6 62.175,76.125 v1@62.2,76.125
  other v1: 62.2,76.1
BUS_A23: U3.B8 U4.F26 | length 50.8
  Top Layer w0.127: U4.F26@51.2,44.9 51.7,44.9 52,45.2 52.8,45.2 53.1,45.2 53.8,45.2 54.1,44.9 55.7,44.9 56.6,45.8 56.6,54.6 57.6,55.6 57.6,57.5 57.8,57.7 57.8,58.4 60.8,61.4 60.8,67.3 61,67.5 61,67.9 60.8,68.1 60.8,71 v1(62.7,72.9) U3.B8@62.7,73.625
  Bottom Layer w0.127: v1(51.8,76.5) 55.725,76.5 55.825,76.6 56.5,76.6 56.7,76.4 56.7,75.8 56.9,75.6 62.5,75.6 62.7,75.4 v1(62.7,72.9)
BUS_A24: U3.C8 U4.E25 | length 49.2
  Top Layer w0.127: U4.E25@50.2,45.9 50.7,46.4 51.225,46.4 51.487,46.4 51.788,46.1 52.8,46.1 53.1,46.1 53.9,46.1 56,48.2 56,57.5 56.2,57.7 56.2,58.4 59.2,61.4 59.2,70.7 v1(61.4,72.9) 61.7,73.2 U3.C8@61.7,73.625
  Bottom Layer w0.127: v1(50.6,76.5) 53.6,73.6 58.5,73.6 59.5,74.6 61.5,74.6 61.7,74.4 61.7,73.2 v1(61.4,72.9)
BUS_D0: U3.E3 U4.E20 U7.2 U11.7 | length 100.8
  Top Layer w0.127: U7.2@34.6,87.7 v2(34.6,89) ; U11.7@62.5,87.7 v1(62.5,88.9) 62.5,89.4 64.1,91 64.7,91 v2(66.9,93.2)
  Top Layer w0.2: U4.E20@45.2,45.9 v1(45.7,46.4) ; v1(59.2,79.1) U3.E3@59.7,78.625
  MidLayer1 w0.127: v2(34.6,89) 34.6,89.5 37.6,92.5 56.8,92.5 57,92.7 66.4,92.7 v2(66.9,93.2) ; v1(59.2,79.1) 57.7,80.6 57.7,83.4 59.2,84.9 62.3,84.9 62.8,85.4 62.8,86 63,86.2 63,86.6 62.5,87.1 v1(62.5,88.9)
  MidLayer2 w0.127: v1(45.7,46.4) 46.2,46.9 46.2,51.5 46.2,51.8 46.2,53.1 48.8,55.7 51.4,55.7 51.7,56 52.6,56 52.8,56.2 52.8,57.5 53.1,57.8 53.1,67.7 52.8,68 52.8,68.5 53.2,68.9 ; 52.95,68.65 57.7,73.4 57.7,78.4 57.9,78.6 58.475,78.6 58.975,79.1 v1(59.2,79.1)
BUS_D1: U3.H3 U4.B20 U7.4 U11.8 | length 95.1
  Top Layer w0.127: U7.4@36.2,87.7 v2(36.2,89) ; U4.B20@45.2,48.9 45.7,49.4 45.7,50.3 46.2,50.8 46.2,51.5 46.2,51.8 46.2,54.9 47.5,56.2 47.5,57.4 47.2,57.7 47.2,58.1 52.8,63.7 52.8,68.5 54.3,70 54.3,74.918 55,75.618 55,77.9 v1(56.2,79.1) ; U11.8@63.3,87.7 v1(63.3,89.5) 64.4,90.6 65.1,90.6 67.7,93.2 v2(67.7,93.8)
  Top Layer w0.2: v1(56.2,79.1) U3.H3@56.7,78.625
  MidLayer1 w0.127: v2(36.2,89) 36.2,89.5 38.9,92.2 57,92.2 57.2,92.4 66.8,92.4 67.7,93.3 v2(67.7,93.8) ; v1(56.2,79.1) 56.7,79.6 56.7,82.9 59.1,85.3 61.9,85.3 62.2,85.6 62.2,86 62,86.2 62,89.1 62.4,89.5 v1(63.3,89.5)
BUS_D2: U3.E4 U4.E22 U7.5 U11.9 | length 97.6
  Top Layer w0.127: U7.5@37,87.7 v2(37,89.6) ; U11.9@64.1,87.7 64.1,89.4 64.7,90 65.3,90 v2(68.5,93.2)
  Top Layer w0.2: U4.E22@47.2,45.9 v1(47.7,46.4) ; U3.E4@59.7,77.625 v1(60.2,78.1)
  MidLayer1 w0.127: v2(37,89.6) 39.3,91.9 57.2,91.9 57.4,92.1 67.4,92.1 v2(68.5,93.2) ; v1(60.2,78.1) 59.7,78.6 59.7,81.5 60.1,81.9 62.4,81.9 63.8,83.3 63.8,85.3 64.7,86.2 64.7,88.3 v1(64.1,88.9)
  MidLayer2 w0.127: v1(47.7,46.4) 48.2,46.9 48.2,51.5 48.2,51.8 48.2,52.1 49.5,53.4 51,53.4 51.8,54.2 52.4,54.2 54.4,56.2 54.4,57.5 54.6,57.7 54.6,67.9 54.3,68.2 54.3,68.8 57.6,72.1 58.7,72.1 58.9,72.3 59.2,72.6 59.2,73.7 59.7,74.2 59.7,77.6 v1(60.2,78.1)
